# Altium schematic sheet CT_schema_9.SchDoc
size 281 x 153 mm
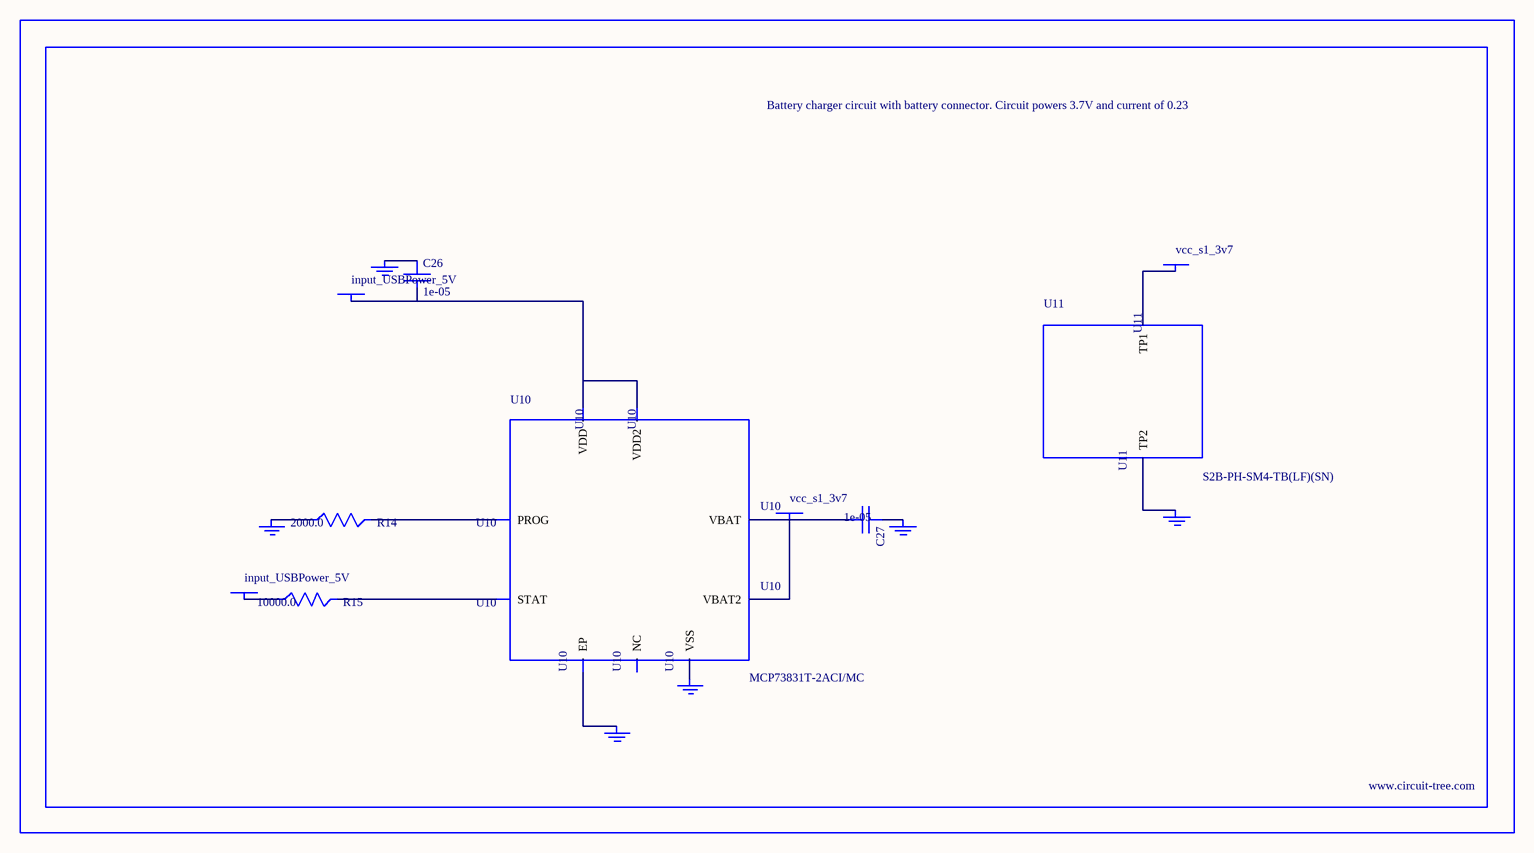
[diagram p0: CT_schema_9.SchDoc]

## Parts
BORDER8  (no value)
C26  1e-05  [C1206]
C27  1e-05  [C1206]
GND_INSTANCE_8_0  (no value)
GND_INSTANCE_8_1  (no value)
GND_INSTANCE_8_2  (no value)
GND_INSTANCE_8_3  (no value)
GND_INSTANCE_8_4  (no value)
GND_INSTANCE_8_5  (no value)
POWER_INSTANCE_8_0  input_USBPower_5V
POWER_INSTANCE_8_1  input_USBPower_5V
POWER_INSTANCE_8_2  vcc_s1_3v7
POWER_INSTANCE_8_3  vcc_s1_3v7
R14  2000.0  [R0603]
R15  10000.0  [R0603]
U10  MCP73831T-2ACI/MC  [DFN8_2X3MC]
U11  S2B-PH-SM4-TB(LF)(SN)  [JST-2-SMD]

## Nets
NetC26_1: C26.1 GND_INSTANCE_8_0.0(GND)
NetC26_2: C26.2 POWER_INSTANCE_8_0.0(PWR) U10.1(VDD) U10.2(VDD2)
NetC27_1: C27.1 GND_INSTANCE_8_1.0(GND)
NetC27_2: C27.2 POWER_INSTANCE_8_2.0(PWR) U10.3(VBAT) U10.4(VBAT2)
NetGND_INSTANCE_8_2_0: GND_INSTANCE_8_2.0(GND) R14.1
NetGND_INSTANCE_8_3_0: GND_INSTANCE_8_3.0(GND) U10.9(EP)
NetGND_INSTANCE_8_4_0: GND_INSTANCE_8_4.0(GND) U10.6(VSS)
NetGND_INSTANCE_8_5_0: GND_INSTANCE_8_5.0(GND) U11.2(TP2)
NetPOWER_INSTANCE_8_1_0: POWER_INSTANCE_8_1.0(PWR) R15.1
NetPOWER_INSTANCE_8_3_0: POWER_INSTANCE_8_3.0(PWR) U11.1(TP1)
NetR14_2: R14.2 U10.8(PROG)
NetR15_2: R15.2 U10.5(STAT)

Not connected (* = marked no-connect by the designer): U10 7(NC)

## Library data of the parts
BORDER8 = BORDER_PAGE8
C26 C27 = C1206C106K3RACTU
GND_INSTANCE_8_0-GND_INSTANCE_8_5 = GND
POWER_INSTANCE_8_0-POWER_INSTANCE_8_3 = PWR
R14 = RC0603JR-072KL
R15 = RC0603JR-0710KL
